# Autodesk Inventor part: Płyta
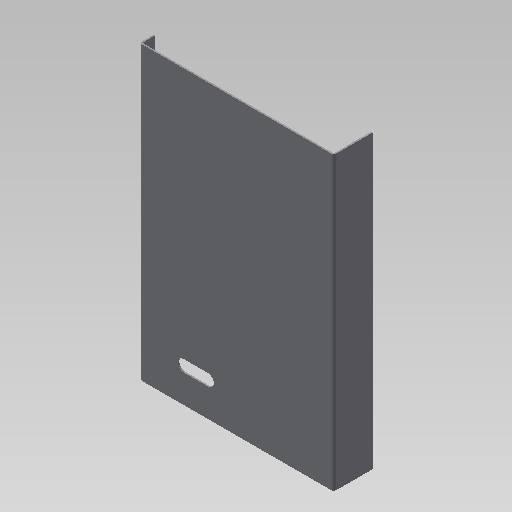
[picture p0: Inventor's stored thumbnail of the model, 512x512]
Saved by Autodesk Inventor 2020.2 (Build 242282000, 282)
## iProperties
Created: 2014-09
Part Number: Płyta
Material: Ogólny
Document SubType Name: Konstrukcja blachowa
Designer: F.Stasiak
Density: 1 g/cm^3
Sheet Metal Rule: Domyślny_mm
Appearance: Domyślna
Catalog Web Link: www.expertbooks.pl
Manager: www.cadconsulting.pl
Company: Fabian Stasiak CAD Consulting
Author: F.Stasiak
Subject: Zbiór ćwiczeń. Autodesk Inventor 2020. Kurs Professional
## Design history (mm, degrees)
node "Powierzchnia1"
  sketch "Szkic2"
    geometry: L1 (-100, 150)-(100, 150); L2 (100, 150)-(100, -150); L3 (100, -150)-(-100, -150); L4 (-100, -150)-(-100, 150); 3 further points
    constraints: 8 end point, 2 midpoint, 2 parallel, 1 horizontal, 1 horizontal alignment, 1 perpendicular, 1 vertical alignment
    dimensions: "d0" = 200 distance of L2.end L3.end; "d1" = 300 distance of L1.end L2.end
node "Kołnierz1"
node "Kołnierz4"
sketch "Szkic7"
  geometry: L1 (-54.5, -115)-(-29.5, -115); L2 (-54.5, -121)-(-29.5, -121); L3 (-29.5, -109)-(-54.5, -109); L4 (-97, 150)-(-97, -150) reference; L5 (97, -150)-(-97, -150) reference; L6 (97, -150)-(97, 150) reference; L7 (-97, 150)-(97, 150) reference; A1 r 6 centre (-54.5, -115) between (-54.5, -109) and (-54.5, -121); A2 r 6 centre (-29.5, -115) between (-29.5, -121) and (-29.5, -109); 2 further points
  constraints: 8 end point, 4 point on circle, 4 tangent, 2 centre point, 1 horizontal, 1 midpoint, 1 parallel
  dimensions: "d43" = 12 diameter of A2; "d44" = 25 distance of L3.start L3.end; "d47" = 35 distance between parallel lines of L5 L1; "d48" = 55 distance from line of L4 point (-42, -115)
feature "Wytnij1" sketch "Szkic7" dims "d45" = 1.5 (= Grubość), "d46" = 0
node "Bryła1"
feature "Płyta1" dims "d57" = 1.5 (= Grubość)
sketch "Szkic3"
  geometry: L1 (0, -40)-(300, -40); L2 (300, -40)-(300, 0); 1 other entity
  constraints: 4 end point, 4 other
feature "Płyta2" dims "d3" = 1.5 (= SzerokośćGięciaPodcięcia), "d4" = 0.75 (= GłębokośćGięciaPodcięcia), "d5" = 3 (= MinimalnaPozostałość), "d6" = 1.5 (= PromieńGięcia), "d7" = 40, "d8" = 90 deg, "d9" = 1.5 (= PromieńGięcia), "d10" = 6 (= RozmiarPodcięciaNarożnika), "d11" = 1.5 (= Wielk_odstępu), "d12" = 1.5 (= Rozmiar_promienia_Jacobiego), "d57" = 1.5 (= Grubość), "OdstępPołączenia" = 0.01
feature "Gięcie1" dims "d3" = 1.5 (= SzerokośćGięciaPodcięcia), "d4" = 0.75 (= GłębokośćGięciaPodcięcia), "d5" = 3 (= MinimalnaPozostałość), "d6" = 1.5 (= PromieńGięcia), "d7" = 40, "d8" = 90 deg, "d9" = 1.5 (= PromieńGięcia), "d57" = 1.5 (= Grubość), "OdstępPołączenia" = 0.01
feature "Narożnik1" dims "d7" = 40, "d8" = 90 deg, "d10" = 6 (= RozmiarPodcięciaNarożnika), "d11" = 1.5 (= Wielk_odstępu), "d12" = 1.5 (= Rozmiar_promienia_Jacobiego)
sketch "Szkic6"
  geometry: L1 (0, -15)-(300, -15); L2 (300, -15)-(300, 0); 1 other entity
  constraints: 4 end point, 4 other
feature "Płyta5" dims "d33" = 1.5 (= SzerokośćGięciaPodcięcia), "d34" = 0.75 (= GłębokośćGięciaPodcięcia), "d35" = 3 (= MinimalnaPozostałość), "d36" = 1.5 (= PromieńGięcia), "d37" = 15, "d38" = 90 deg, "d39" = 1.5 (= PromieńGięcia), "d40" = 6 (= RozmiarPodcięciaNarożnika), "d41" = 1.5 (= Wielk_odstępu), "d42" = 1.5 (= Rozmiar_promienia_Jacobiego), "d57" = 1.5 (= Grubość), "OdstępPołączenia" = 0.01
feature "Gięcie4" dims "d33" = 1.5 (= SzerokośćGięciaPodcięcia), "d34" = 0.75 (= GłębokośćGięciaPodcięcia), "d35" = 3 (= MinimalnaPozostałość), "d36" = 1.5 (= PromieńGięcia), "d37" = 15, "d38" = 90 deg, "d39" = 1.5 (= PromieńGięcia), "d57" = 1.5 (= Grubość), "OdstępPołączenia" = 0.01
feature "Narożnik4" dims "d37" = 15, "d38" = 90 deg, "d40" = 6 (= RozmiarPodcięciaNarożnika), "d41" = 1.5 (= Wielk_odstępu), "d42" = 1.5 (= Rozmiar_promienia_Jacobiego)
node "Pętla rzutowana1"
other parameters: "Grubość" = 1.5 (derived), "WspółczynnikK" = 4.4, "PromieńGięcia" = 1.5 (= Grubość), "SzerokośćGięciaPodcięcia" = 1.5 (= Grubość), "GłębokośćGięciaPodcięcia" = 0.75 (= 0.5 x Grubość), "RozmiarPodcięciaNarożnika" = 6 (= 4 x Grubość), "MinimalnaPozostałość" = 3 (= 2 x Grubość), "PromieńPrzejścia" = 1.5 (= PromieńGięcia), "Rozmiar_promienia_Jacobiego" = 1.5 (= PromieńGięcia), "Wielk_odstępu" = 1.5 (= Grubość), "d2" = 1.5 (= PromieńGięcia)
